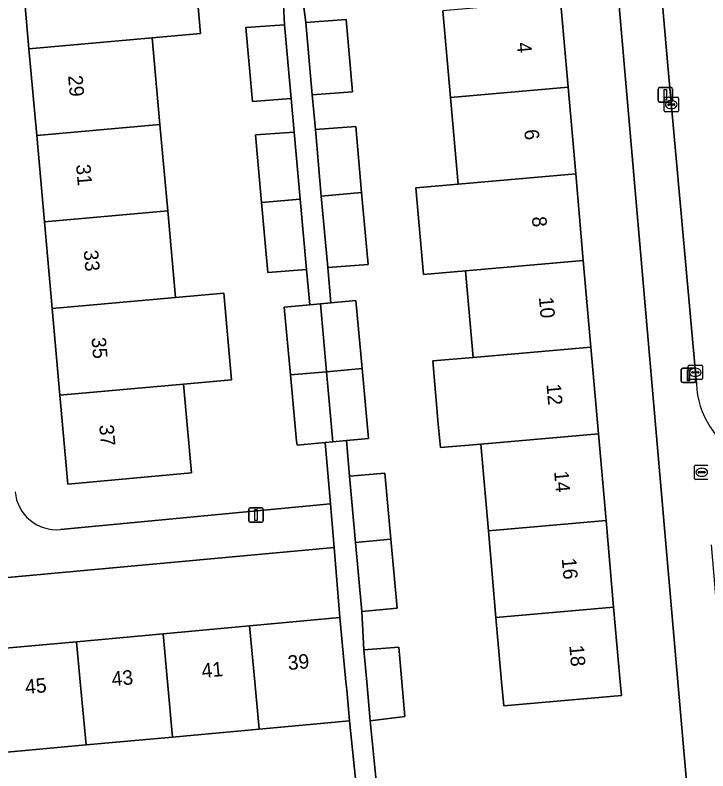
# Model space of a CAD drawing. Extents: x 160554 to 161248, y 385329 to 386506.
# Drawn here: x 160949.5 to 160997.3, y 385493.8 to 385546 of the extents above; entities that cross this region are included whole.
import ezdxf

# ---------------------------------------------------------------- set-up
doc = ezdxf.new("R2010")
doc.units = 0
for name, color, linetype in [('IMGEO_Erf', 7, 'Continuous'), ('IMGEO_Kolk', 7, 'Continuous'), ('IMGEO_Lichtmast', 7, 'Continuous'), ('IMGEO_Pand', 7, 'Continuous'), ('IMGEO_Pand_nummerreeks', 7, 'Continuous'), ('IMGEO_Rijbaan_lokaal_open', 7, 'Continuous'), ('IMGEO_Rioolput', 7, 'Continuous'), ('IMGEO_Voetpad_open', 7, 'Continuous')]:
    doc.layers.add(name, color=color, linetype=linetype)

msp = doc.modelspace()

# ---------------------------------------------------------------- linework, layer by layer
at = {"layer": 'IMGEO_Erf'}
for points in [[(160966.078, 385537.713), (160968.75, 385537.917), (160968.543, 385540.222), (160965.872, 385540.019), (160965.415, 385545.119), (160968.087, 385545.322), (160968.006, 385546.698), (160965.458, 385546.504), (160965.121, 385550.92), (160967.67, 385551.097), (160967.302, 385555.272), (160948.115, 385553.564)], [(160996.184, 385489.155), (160995.24, 385500), (160990.465, 385554.835)], [(160969.366, 385546.867), (160969.547, 385545.475), (160972.334, 385545.688), (160972.781, 385540.695), (160969.994, 385540.482), (160970.209, 385538.085), (160972.996, 385538.298), (160973.403, 385533.746), (160973.847, 385528.789), (160971.061, 385528.577), (160971.288, 385526.143), (160972.998, 385526.303), (160973.435, 385521.598), (160973.884, 385516.773), (160972.356, 385516.631), (160972.561, 385514.167), (160974.996, 385514.393), (160975.42, 385509.823), (160975.86, 385505.075), (160973.425, 385504.85), (160973.568, 385502.193), (160975.969, 385502.386), (160976.18, 385500), (160976.392, 385497.595), (160974.003, 385497.288), (160975, 385487.181)], [(160987.139, 385546.989), (160987.662, 385541.012), (160988.185, 385535.035), (160988.708, 385529.058), (160989.231, 385523.08), (160989.754, 385517.103), (160990.277, 385511.126), (160990.8, 385505.149), (160991.25, 385500), (160991.334, 385499.043), (160983.212, 385498.336), (160983.068, 385500), (160982.679, 385504.438), (160982.156, 385510.415), (160981.633, 385516.392), (160978.842, 385516.148), (160978.699, 385517.774), (160978.318, 385522.125), (160981.11, 385522.369), (160980.586, 385528.347), (160977.668, 385528.091), (160977.144, 385534.069), (160980.063, 385534.324), (160979.54, 385540.301), (160979.017, 385546.278)], [(160952.62, 385510.494), (160971.25, 385512.259), (160970.898, 385516.496), (160968.944, 385516.313), (160968.919, 385516.582), (160968.493, 385521.158), (160968.057, 385525.842), (160969.825, 385526.007), (160969.599, 385528.431), (160966.928, 385528.227), (160966.496, 385533.047), (160966.078, 385537.713)], [(160973.383, 385489.523), (160972.572, 385497.288), (160966.327, 385496.722), (160960.352, 385496.18), (160954.377, 385495.638), (160948.4, 385495.096), (160942.425, 385494.554), (160936.449, 385494.013), (160935.207, 385493.9), (160930.227, 385493.449), (160929.632, 385500), (160929.582, 385500.547), (160935.799, 385501.116), (160941.774, 385501.662), (160947.749, 385502.209), (160953.725, 385502.756), (160959.7, 385503.302), (160965.675, 385503.849), (160971.897, 385504.418), (160971.5, 385509.25), (160925.409, 385505.018)]]:
    msp.add_lwpolyline(points, dxfattribs=at)
msp.add_lwpolyline([(160959.481, 385538.447), (160960.023, 385532.472), (160960.566, 385526.495), (160963.886, 385526.791), (160964.418, 385520.815), (160961.108, 385520.52), (160961.664, 385514.396), (160953.115, 385513.635), (160952.57, 385519.759), (160952.038, 385525.735), (160951.506, 385531.712), (160950.973, 385537.688), (160950.441, 385543.664), (160949.896, 385549.79), (160958.383, 385550.545), (160958.394, 385550.42), (160961.746, 385550.718), (160962.291, 385544.721), (160958.939, 385544.422)], close=True, dxfattribs=at)
msp.add_arc((160952.348, 385513.36), 2.879, 185.2998, 275.4131, dxfattribs=at)
at = {"layer": 'IMGEO_Kolk'}
for p, q in [((160994.281, 385539.389), (160994.281, 385540.241)), ((160994.356, 385540.315), (160995.208, 385540.315)), ((160994.769, 385540.095), (160994.794, 385540.095)), ((160995.282, 385540.241), (160995.282, 385539.389)), ((160994.54, 385539.809), (160994.54, 385539.821)), ((160994.978, 385539.772), (160994.58, 385539.772)), ((160994.583, 385539.858), (160994.981, 385539.858)), ((160994.792, 385539.535), (160994.767, 385539.535)), ((160995.024, 385539.821), (160995.024, 385539.809)), ((160995.208, 385539.315), (160994.356, 385539.315)), ((160996.015, 385521.84), (160996.867, 385521.84)), ((160995.94, 385520.914), (160995.94, 385521.766)), ((160996.199, 385521.334), (160996.199, 385521.346)), ((160996.637, 385521.297), (160996.239, 385521.297)), ((160996.242, 385521.383), (160996.64, 385521.383)), ((160996.428, 385521.62), (160996.453, 385521.62)), ((160996.683, 385521.346), (160996.683, 385521.334)), ((160996.941, 385521.766), (160996.941, 385520.914)), ((160996.867, 385520.84), (160996.015, 385520.84)), ((160996.451, 385521.06), (160996.426, 385521.06))]:
    msp.add_line(p, q, dxfattribs=at)
for points in [[(160994.281, 385539.389), (160994.281, 385540.241)], [(160994.356, 385540.315), (160995.208, 385540.315)], [(160995.282, 385540.241), (160995.282, 385539.389)], [(160995.208, 385539.315), (160994.356, 385539.315)], [(160996.015, 385521.84), (160996.867, 385521.84)], [(160995.94, 385520.914), (160995.94, 385521.766)], [(160996.941, 385521.766), (160996.941, 385520.914)], [(160996.867, 385520.84), (160996.015, 385520.84)]]:
    msp.add_lwpolyline(points, dxfattribs=at)
for centre, radius, start, end in [((160994.358, 385540.239), 0.0765, 91.552, 178.448), ((160994.358, 385540.239), 0.0765, 91.552, 178.448), ((160995.206, 385540.239), 0.0765, 1.552, 88.448), ((160995.206, 385540.239), 0.0765, 1.552, 88.448), ((160994.58, 385539.818), 0.0403, 85.8775, 175.7526), ((160994.577, 385539.808), 0.0366, 178.938, 274.7102), ((160994.981, 385539.815), 0.043, 264.8664, 352.4533), ((160994.985, 385539.82), 0.0386, 1.7309, 96.639), ((160994.358, 385539.391), 0.0765, 181.552, 268.448), ((160994.358, 385539.391), 0.0765, 181.552, 268.448), ((160995.206, 385539.391), 0.0765, 271.552, 358.448), ((160995.206, 385539.391), 0.0765, 271.552, 358.448), ((160996.017, 385521.764), 0.0765, 91.552, 178.448), ((160996.017, 385521.764), 0.0765, 91.552, 178.448), ((160996.865, 385521.764), 0.0765, 1.552, 88.448), ((160996.865, 385521.764), 0.0765, 1.552, 88.448), ((160996.239, 385521.343), 0.0403, 85.8775, 175.7526), ((160996.236, 385521.333), 0.0366, 178.938, 274.7102), ((160996.64, 385521.34), 0.043, 264.8664, 352.4533), ((160996.644, 385521.345), 0.0386, 1.7309, 96.639), ((160996.017, 385520.916), 0.0765, 181.552, 268.448), ((160996.017, 385520.916), 0.0765, 181.552, 268.448), ((160996.865, 385520.916), 0.0765, 271.552, 358.448), ((160996.865, 385520.916), 0.0765, 271.552, 358.448)]:
    msp.add_arc(centre, radius, start, end, dxfattribs=at)
for centre, major_axis, ratio, start_param, end_param in [((160994.768, 385539.815), (-0.387, 0.002), 0.722429, 4.712389, 7.853982), ((160994.793, 385539.815), (-0.39, 0.002), 0.717154, 1.570796, 4.712389), ((160996.427, 385521.34), (-0.387, 0.002), 0.722429, 4.712389, 7.853982), ((160996.452, 385521.34), (-0.39, 0.002), 0.717154, 1.570796, 4.712389)]:
    msp.add_ellipse(centre, major_axis=major_axis, ratio=ratio, start_param=start_param, end_param=end_param, dxfattribs=at)
at = {"layer": 'IMGEO_Lichtmast'}
for p, q in [((160993.879, 385540.085), (160993.879, 385540.885)), ((160993.879, 385540.885), (160993.879, 385540.085)), ((160993.979, 385540.985), (160994.769, 385540.985)), ((160994.769, 385540.985), (160993.979, 385540.985)), ((160994.869, 385540.885), (160994.869, 385540.085)), ((160994.869, 385540.085), (160994.869, 385540.885)), ((160994.769, 385539.985), (160993.979, 385539.985)), ((160993.979, 385539.985), (160994.769, 385539.985)), ((160995.472, 385520.731), (160995.472, 385521.531)), ((160995.472, 385521.531), (160995.472, 385520.731)), ((160995.572, 385521.631), (160996.362, 385521.631)), ((160996.362, 385521.631), (160995.572, 385521.631)), ((160996.462, 385521.531), (160996.462, 385520.731)), ((160996.462, 385520.731), (160996.462, 385521.531)), ((160996.362, 385520.631), (160995.572, 385520.631)), ((160995.572, 385520.631), (160996.362, 385520.631)), ((160965.613, 385511.093), (160965.613, 385511.893)), ((160965.613, 385511.893), (160965.613, 385511.093)), ((160965.713, 385511.993), (160966.503, 385511.993)), ((160966.503, 385511.993), (160965.713, 385511.993)), ((160966.603, 385511.893), (160966.603, 385511.093)), ((160966.603, 385511.093), (160966.603, 385511.893)), ((160966.503, 385510.993), (160965.713, 385510.993)), ((160965.713, 385510.993), (160966.503, 385510.993))]:
    msp.add_line(p, q, dxfattribs=at)
for points in [[(160994.299, 385540.86), (160994.449, 385540.86), (160994.449, 385540.11), (160994.299, 385540.11), (160994.299, 385540.86)], [(160995.892, 385521.506), (160996.042, 385521.506), (160996.042, 385520.756), (160995.892, 385520.756), (160995.892, 385521.506)], [(160966.033, 385511.868), (160966.183, 385511.868), (160966.183, 385511.118), (160966.033, 385511.118), (160966.033, 385511.868)]]:
    msp.add_lwpolyline(points, dxfattribs=at)
for centre, start, end in [((160993.979, 385540.885), 90, 180), ((160993.979, 385540.885), 90, 180), ((160994.769, 385540.885), 0, 90), ((160994.769, 385540.885), 360, 90), ((160993.979, 385540.085), 180, 270), ((160993.979, 385540.085), 180, 270), ((160994.769, 385540.085), 270, 0), ((160994.769, 385540.085), 270, 0), ((160995.572, 385521.531), 90, 180), ((160995.572, 385521.531), 90, 180), ((160996.362, 385521.531), 0, 90), ((160996.362, 385521.531), 360, 90), ((160995.572, 385520.731), 180, 270), ((160995.572, 385520.731), 180, 270), ((160996.362, 385520.731), 270, 0), ((160996.362, 385520.731), 270, 0), ((160965.713, 385511.893), 90, 180), ((160965.713, 385511.893), 90, 180), ((160966.503, 385511.893), 0, 90), ((160966.503, 385511.893), 360, 90), ((160965.713, 385511.093), 180, 270), ((160965.713, 385511.093), 180, 270), ((160966.503, 385511.093), 270, 0), ((160966.503, 385511.093), 270, 0)]:
    msp.add_arc(centre, 0.1, start, end, dxfattribs=at)
at = {"layer": 'IMGEO_Pand'}
for points in [[(160961.746, 385550.718), (160958.394, 385550.42), (160958.383, 385550.545), (160949.896, 385549.79), (160950.441, 385543.664), (160958.939, 385544.422), (160962.291, 385544.721)], [(160987.662, 385541.012), (160987.139, 385546.989), (160979.017, 385546.278), (160979.54, 385540.301)], [(160965.415, 385545.119), (160965.872, 385540.019), (160968.543, 385540.222), (160968.087, 385545.322)], [(160972.781, 385540.695), (160972.334, 385545.688), (160969.547, 385545.475), (160969.994, 385540.482)], [(160950.441, 385543.664), (160950.973, 385537.688), (160959.481, 385538.447), (160958.939, 385544.422)], [(160979.54, 385540.301), (160980.063, 385534.324), (160988.185, 385535.035), (160987.662, 385541.012)], [(160960.023, 385532.472), (160959.481, 385538.447), (160950.973, 385537.688), (160951.506, 385531.712)], [(160973.403, 385533.746), (160972.996, 385538.298), (160970.209, 385538.085), (160970.62, 385533.502)], [(160969.165, 385533.285), (160968.75, 385537.917), (160966.078, 385537.713), (160966.496, 385533.047)], [(160988.185, 385535.035), (160980.063, 385534.324), (160977.144, 385534.069), (160977.668, 385528.091), (160980.586, 385528.347), (160988.708, 385529.058)], [(160966.496, 385533.047), (160966.928, 385528.227), (160969.599, 385528.431), (160969.165, 385533.285)], [(160970.62, 385533.502), (160971.061, 385528.577), (160973.847, 385528.789), (160973.403, 385533.746)], [(160951.506, 385531.712), (160952.038, 385525.735), (160960.566, 385526.495), (160960.023, 385532.472)], [(160989.231, 385523.08), (160988.708, 385529.058), (160980.586, 385528.347), (160981.11, 385522.369)], [(160960.566, 385526.495), (160952.038, 385525.735), (160952.57, 385519.759), (160961.108, 385520.52), (160964.418, 385520.815), (160963.886, 385526.791)], [(160970.563, 385526.076), (160969.825, 385526.007), (160968.057, 385525.842), (160968.493, 385521.158), (160970.989, 385521.38)], [(160970.989, 385521.38), (160973.435, 385521.598), (160972.998, 385526.303), (160971.288, 385526.143), (160970.563, 385526.076)], [(160989.231, 385523.08), (160981.11, 385522.369), (160978.318, 385522.125), (160978.699, 385517.774), (160978.842, 385516.148), (160981.633, 385516.392), (160989.754, 385517.103)], [(160970.989, 385521.38), (160968.493, 385521.158), (160968.919, 385516.582), (160968.944, 385516.313), (160970.898, 385516.496), (160971.428, 385516.545)], [(160973.435, 385521.598), (160970.989, 385521.38), (160971.428, 385516.545), (160972.356, 385516.631), (160973.884, 385516.773)], [(160952.57, 385519.759), (160953.115, 385513.635), (160961.664, 385514.396), (160961.108, 385520.52)], [(160990.277, 385511.126), (160989.754, 385517.103), (160981.633, 385516.392), (160982.156, 385510.415)], [(160975.42, 385509.823), (160974.996, 385514.393), (160972.561, 385514.167), (160972.984, 385509.61)], [(160982.156, 385510.415), (160982.679, 385504.438), (160990.8, 385505.149), (160990.277, 385511.126)], [(160972.984, 385509.61), (160973.425, 385504.85), (160975.86, 385505.075), (160975.42, 385509.823)], [(160982.679, 385504.438), (160983.068, 385500), (160983.212, 385498.336), (160991.334, 385499.043), (160991.25, 385500), (160990.8, 385505.149)], [(160966.027, 385500), (160966.327, 385496.722), (160972.572, 385497.288), (160972.378, 385499.442), (160972.324, 385500), (160971.897, 385504.418), (160965.675, 385503.849)], [(160960.002, 385500), (160960.352, 385496.18), (160966.327, 385496.722), (160966.027, 385500), (160965.675, 385503.849), (160959.7, 385503.302)], [(160953.977, 385500), (160954.377, 385495.638), (160960.352, 385496.18), (160960.002, 385500), (160959.7, 385503.302), (160953.725, 385502.756)], [(160953.725, 385502.756), (160947.749, 385502.209), (160947.951, 385500), (160948.4, 385495.096), (160954.377, 385495.638), (160953.977, 385500)], [(160976.392, 385497.595), (160976.18, 385500), (160975.969, 385502.386), (160973.568, 385502.193), (160973.762, 385500), (160974.003, 385497.288)]]:
    msp.add_lwpolyline(points, close=True, dxfattribs=at)
at = {"layer": 'IMGEO_Rijbaan_lokaal_open'}
msp.add_lwpolyline([(160997.404, 385588.195), (160996.464, 385600.472), (160995.606, 385610.352), (160995.517, 385611.683), (160988.57, 385611.128), (160988.633, 385610.652), (160989.182, 385604.198), (160990.456, 385589.389), (160990.78, 385585.63), (160990.883, 385584.43), (160991.222, 385580.549), (160994.544, 385542.485), (160996.512, 385520.561)], dxfattribs=at)
msp.add_arc((161002.387, 385520.786), 5.88, 182.1925, 243.5454, dxfattribs=at)
at = {"layer": 'IMGEO_Rioolput'}
for p, q in [((160996.382, 385514.02), (160996.382, 385514.872)), ((160996.457, 385514.946), (160997.309, 385514.946)), ((160996.684, 385514.489), (160997.082, 385514.489)), ((160996.87, 385514.726), (160996.895, 385514.726)), ((160996.641, 385514.44), (160996.641, 385514.452)), ((160997.079, 385514.403), (160996.681, 385514.403)), ((160996.893, 385514.166), (160996.868, 385514.166)), ((160997.125, 385514.452), (160997.125, 385514.44)), ((160997.309, 385513.946), (160996.457, 385513.946))]:
    msp.add_line(p, q, dxfattribs=at)
for points in [[(160996.382, 385514.02), (160996.382, 385514.872)], [(160996.457, 385514.946), (160997.309, 385514.946)], [(160997.309, 385513.946), (160996.457, 385513.946)]]:
    msp.add_lwpolyline(points, dxfattribs=at)
for centre, radius, start, end in [((160996.459, 385514.87), 0.0765, 91.552, 178.448), ((160996.459, 385514.87), 0.0765, 91.552, 178.448), ((160996.681, 385514.449), 0.0403, 85.8775, 175.7526), ((160997.086, 385514.451), 0.0386, 1.7309, 96.639), ((160996.459, 385514.022), 0.0765, 181.552, 268.448), ((160996.459, 385514.022), 0.0765, 181.552, 268.448), ((160996.678, 385514.439), 0.0366, 178.938, 274.7102), ((160997.082, 385514.446), 0.043, 264.8664, 352.4533)]:
    msp.add_arc(centre, radius, start, end, dxfattribs=at)
for centre, major_axis, ratio, start_param, end_param in [((160996.869, 385514.446), (-0.387, 0.002), 0.722429, 4.712389, 7.853982), ((160996.894, 385514.446), (-0.39, 0.002), 0.717154, 1.570796, 4.712389)]:
    msp.add_ellipse(centre, major_axis=major_axis, ratio=ratio, start_param=start_param, end_param=end_param, dxfattribs=at)
at = {"layer": 'IMGEO_Voetpad_open'}
for points in [[(160985.493, 385610.427), (160987.439, 385588.591), (160987.689, 385585.785), (160987.694, 385585.726), (160987.83, 385584.198), (160988.096, 385581.219), (160989.686, 385563.373), (160989.697, 385563.317), (160990.469, 385555.011), (160990.465, 385554.835), (160995.24, 385500), (160996.184, 385489.155), (160999.286, 385489.399), (160998.37, 385500), (160997.554, 385509.444)], [(160996.512, 385520.561), (160994.544, 385542.485), (160991.222, 385580.549)], [(160925.409, 385505.018), (160971.5, 385509.25), (160971.25, 385512.259), (160952.62, 385510.494)]]:
    msp.add_lwpolyline(points, dxfattribs=at)
for points in [[(160969.547, 385545.475), (160969.366, 385546.867), (160969.065, 385551.194), (160968.699, 385555.397), (160967.302, 385555.272), (160967.67, 385551.097), (160968.006, 385546.698), (160968.087, 385545.322), (160968.543, 385540.222), (160968.75, 385537.917), (160969.165, 385533.285), (160969.599, 385528.431), (160969.825, 385526.007), (160970.563, 385526.076), (160971.288, 385526.143), (160971.061, 385528.577), (160970.62, 385533.502), (160970.209, 385538.085), (160969.994, 385540.482)], [(160973.568, 385502.193), (160973.425, 385504.85), (160972.984, 385509.61), (160972.561, 385514.167), (160972.356, 385516.631), (160971.428, 385516.545), (160970.898, 385516.496), (160971.25, 385512.259), (160971.5, 385509.25), (160971.897, 385504.418), (160972.324, 385500), (160972.378, 385499.442), (160972.572, 385497.288), (160973.383, 385489.523), (160973.601, 385487.051), (160975, 385487.181), (160974.003, 385497.288), (160973.762, 385500)]]:
    msp.add_lwpolyline(points, close=True, dxfattribs=at)
for centre, radius, start, end in [((161002.387, 385520.786), 5.88, 182.1925, 243.5454), ((160952.348, 385513.36), 2.879, 185.2998, 275.4131)]:
    msp.add_arc(centre, radius, start, end, dxfattribs=at)

# ---------------------------------------------------------------- texts
at = {"layer": 'IMGEO_Pand_nummerreeks'}
for s, rotation, p in [('4', 275, (160984.102, 385544.075)), ('29', 275.0878, (160953.137, 385541.798)), ('6', 275, (160984.628, 385538.07)), ('31', 275.0878, (160953.684, 385535.66)), ('8', 275.0017, (160985.153, 385532.059)), ('33', 275.0878, (160954.21, 385529.747)), ('10', 275, (160985.639, 385526.514)), ('35', 275.0877, (160954.747, 385523.721)), ('12', 275.0017, (160986.162, 385520.514)), ('37', 275.0878, (160955.283, 385517.695)), ('14', 275, (160986.689, 385514.505)), ('16', 275, (160987.215, 385508.499)), ('18', 275, (160987.74, 385502.49)), ('39', 5.2269, (160968.345, 385500.799)), ('41', 5.2269, (160962.399, 385500.255)), ('43', 5.2212, (160956.189, 385499.688)), ('45', 5.2299, (160950.214, 385499.142))]:
    msp.add_text(s, height=1, rotation=rotation, dxfattribs=at).set_placement(p)

doc.saveas('drawing.dxf')
